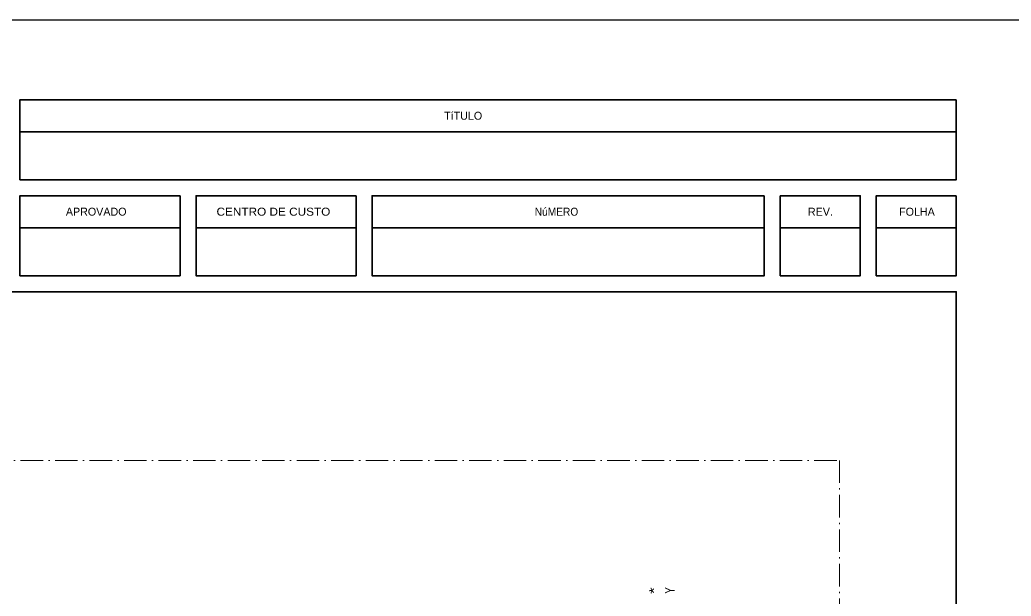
# Model space of a CAD drawing. Extents: x -4160 to -2690, y -474 to 714.
# Drawn here: x -3447.8 to -3323.9, y 642.4 to 714.5 of the extents above; entities that cross this region are included whole.
import ezdxf
from ezdxf.enums import TextEntityAlignment as Align

# ---------------------------------------------------------------- set-up
doc = ezdxf.new("R2010")
doc.units = 0
doc.header["$LTSCALE"] = 0.56
doc.linetypes.add('DOT_DASHED', pattern=[7.7, 5, -1.2, 0.3, -1.2])
doc.layers.add('5', color=7, linetype='Continuous', lineweight=35)

msp = doc.modelspace()

# ---------------------------------------------------------------- linework, layer by layer
at = {"layer": '5'}
for p, q in [((-3447.7642, 700.48), (-3330.7642, 700.48)), ((-3447.7642, 688.48), (-3427.7642, 688.48)), ((-3425.7642, 688.48), (-3405.7642, 688.48)), ((-3403.7642, 688.48), (-3354.7642, 688.48)), ((-3352.7642, 688.48), (-3342.7642, 688.48)), ((-3340.7642, 688.48), (-3330.7642, 688.48))]:
    msp.add_line(p, q, dxfattribs=at)
at = {"layer": '5', "lineweight": 25}
msp.add_lwpolyline([(-3319.7642, 417.48), (-3529.7642, 417.48), (-3529.7642, 714.48), (-3319.7642, 714.48)], close=True, dxfattribs=at)
at = {"layer": '5'}
for points in [[(-3330.7642, 704.48), (-3447.7642, 704.48), (-3447.7642, 694.48), (-3330.7642, 694.48)], [(-3427.7642, 692.48), (-3447.7642, 692.48), (-3447.7642, 682.48), (-3427.7642, 682.48)], [(-3405.7642, 692.48), (-3425.7642, 692.48), (-3425.7642, 682.48), (-3405.7642, 682.48)], [(-3354.7642, 692.48), (-3403.7642, 692.48), (-3403.7642, 682.48), (-3354.7642, 682.48)], [(-3352.7642, 692.48), (-3342.7642, 692.48), (-3342.7642, 682.48), (-3352.7642, 682.48)], [(-3330.7642, 692.48), (-3340.7642, 692.48), (-3340.7642, 682.48), (-3330.7642, 682.48)], [(-3504.7642, 427.48), (-3504.7642, 680.48), (-3330.7642, 680.48), (-3330.7642, 427.48)]]:
    msp.add_lwpolyline(points, close=True, dxfattribs=at)
at = {"layer": '5', "linetype": 'DOT_DASHED', "lineweight": 13}
msp.add_lwpolyline([(-3473.5534, 659.4019), (-3345.3718, 659.4019), (-3345.3718, 458.917), (-3406.2365, 458.917), (-3406.2365, 529.5479), (-3473.5534, 529.5479)], close=True, dxfattribs=at)

# ---------------------------------------------------------------- texts
at = {"layer": '5'}
for s, p in [('TíTULO', (-3392.3847, 701.991)), ('APROVADO', (-3438.2387, 689.9973)), ('REV.', (-3347.7443, 689.9923)), ('FOLHA', (-3335.6809, 689.9923))]:
    msp.add_text(s, height=1, dxfattribs=at).set_placement(p, align=Align.CENTER)
for s, width, p in [('CENTRO DE CUSTO', 1.1, (-3416.0934, 689.9973)), ('NúMERO', 0.95, (-3380.7228, 689.9923))]:
    msp.add_text(s, height=1, dxfattribs=dict(at, width=width)).set_placement(p, align=Align.CENTER)
for s, width, p in [('*', 1.35, (-3367.9375, 643.127)), ('*', 1.35, (-3367.9375, 643.127)), ('Y', 0.75, (-3365.9592, 643.1588)), ('Y', 0.75, (-3365.9592, 643.1588))]:
    msp.add_text(s, height=1.2, rotation=90, dxfattribs=dict(at, width=width)).set_placement(p, align=Align.CENTER)

doc.saveas('drawing.dxf')
